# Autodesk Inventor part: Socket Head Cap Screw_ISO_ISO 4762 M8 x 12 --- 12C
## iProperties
Created: 2011-02
Part Number: Socket Head Cap Screw_ISO_ISO 4762 M8 x 12 --- 12C
Document SubType Name: Modeling
Designer: eric
Density: 1 g/cm^3
Author: eric
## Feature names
1. Base1
